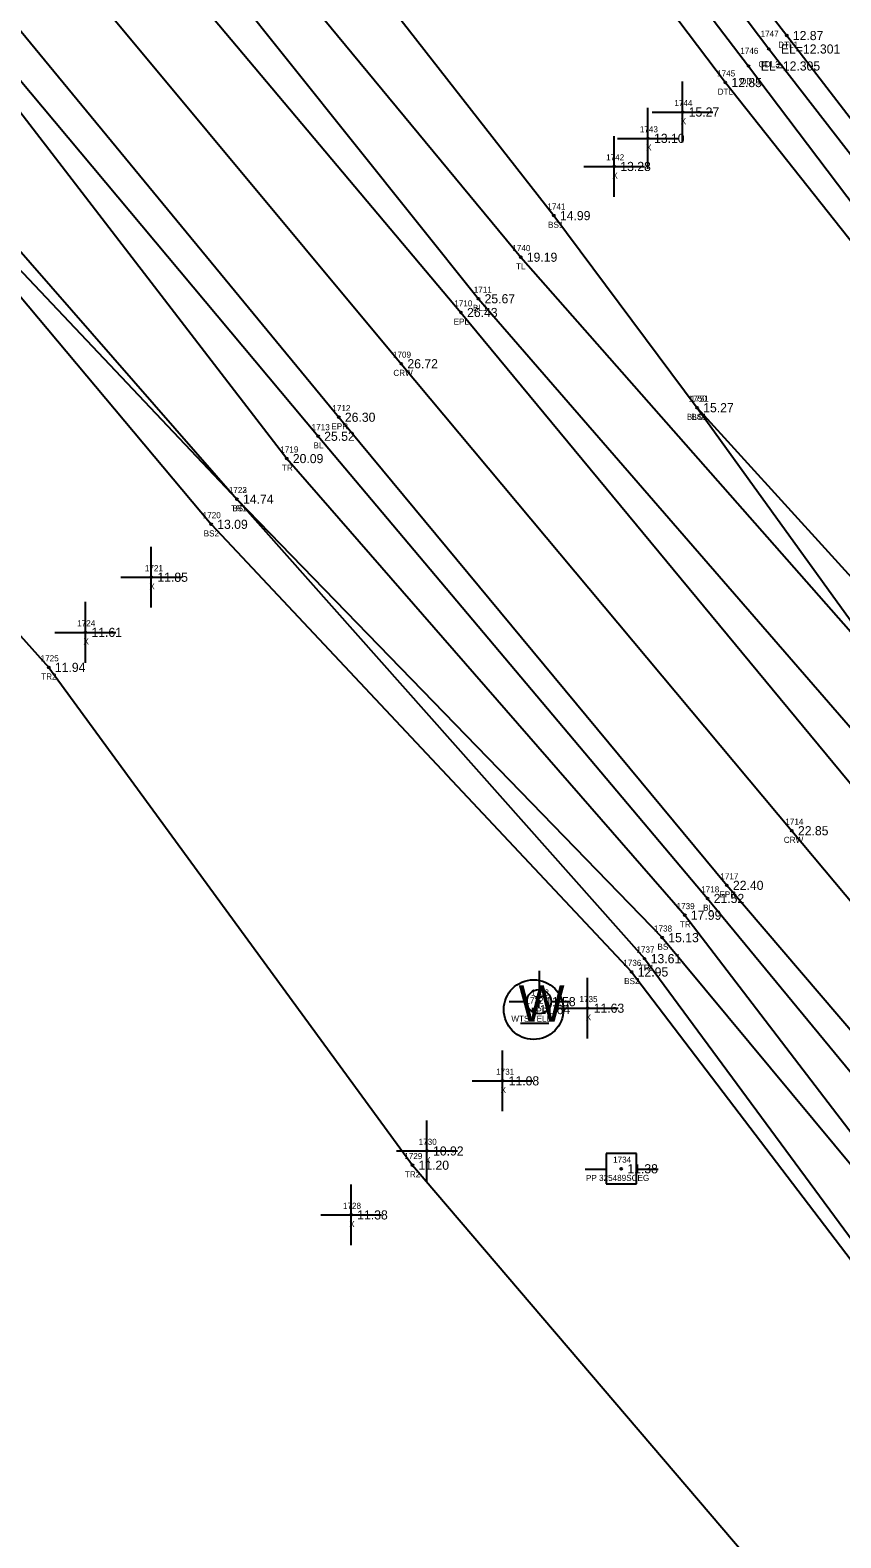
# Model space of a CAD drawing. Extents: x 2042211 to 2045853, y 303080 to 309569.
# Drawn here: x 2043815 to 2043948.3, y 305221.5 to 305469.5 of the extents above; entities that cross this region are included whole.
import ezdxf

# ---------------------------------------------------------------- set-up
doc = ezdxf.new("R2010")
doc.units = 0
for name, color, linetype in [('BR_500YR_SCOUR', 7, 'Continuous'), ('RD_DTM_BkLn1', 7, 'Continuous'), ('RD_DTM_BkLn2', 7, 'Continuous'), ('RD_DTM_BkLn_txCode', 7, 'Continuous'), ('RD_EX_H2O', 7, 'Continuous'), ('RD_EX_H2O_txCode', 7, 'Continuous'), ('RD_EX_Misc', 7, 'Continuous'), ('RD_EX_Misc_txCode', 7, 'Continuous'), ('RD_EX_Road', 7, 'Continuous'), ('RD_EX_Road_txCode', 7, 'Continuous'), ('RD_EX_TX_H2O_ELEV', 7, 'Continuous'), ('RD_EX_TX_Misc_ELEV', 7, 'Continuous'), ('RD_EX_TX_Road_ELEV', 7, 'Continuous'), ('RD_EX_TX_UT_ELEV', 7, 'Continuous'), ('RD_EX_TX_VEG_ELEV', 7, 'Continuous'), ('RD_EX_UT_txCode', 7, 'Continuous'), ('RD_EX_VEG_txCode', 7, 'Continuous'), ('RD_HC_Survey_ELEV', 7, 'Continuous'), ('RD_HC_Survey_txCode', 7, 'Continuous'), ('RD_SMD_Locator', 7, 'Continuous')]:
    doc.layers.add(name, color=color, linetype=linetype)

msp = doc.modelspace()

# ---------------------------------------------------------------- linework, layer by layer
at = {"layer": 'BR_500YR_SCOUR'}
for p, q in [((2043898.65, 305314.79), (2043898.65, 305311.72)), ((2043893.72, 305309.74), (2043896.65, 305309.74)), ((2043900.65, 305309.74), (2043903.72, 305309.74)), ((2043895.62, 305306.2), (2043900.25, 305306.2)), ((2043914.66, 305284.74), (2043909.66, 305284.74)), ((2043909.66, 305284.74), (2043909.66, 305279.74)), ((2043914.66, 305279.74), (2043914.66, 305284.74)), ((2043906.23, 305282.18), (2043909.7, 305282.18)), ((2043914.59, 305282.18), (2043918.23, 305282.18)), ((2043909.66, 305279.74), (2043914.66, 305279.74))]:
    msp.add_line(p, q, dxfattribs=at)
for points in [[(2043547.51, 305881.5), (2043539.7, 305861.32), (2043541.74, 305855.07), (2043567.73, 305828.7), (2043642.4, 305738.29), (2043706.88, 305661.84), (2043768.33, 305586.86), (2043834.29, 305506.38), (2043895.63, 305432.16), (2043964.52, 305353.99), (2044012.41, 305288.23), (2044020.96, 305286.08), (2044026.64, 305287.13), (2044039.88, 305282.36)], [(2043510.52, 305810.42), (2043502.87, 305810.61), (2043504.87, 305802.25), (2043509.11, 305791.37), (2043594.27, 305695.69), (2043658.16, 305620.89), (2043717.86, 305542.89), (2043784.35, 305466.31), (2043848.97, 305392.37), (2043916.01, 305316.79), (2043971.98, 305240.84)], [(2043510.52, 305810.42), (2043528.58, 305788.55), (2043603.52, 305706.8), (2043669.11, 305631.48), (2043746.08, 305529.27), (2043781.83, 305496.01), (2043793.11, 305482.33), (2043857.16, 305399.04), (2043922.61, 305323.93), (2043978.69, 305250.66), (2043978.39, 305246.16), (2043971.98, 305240.84)], [(2043442.97, 305737.07), (2043459.87, 305757.29), (2043500.33, 305735.55), (2043510.29, 305716.16), (2043558.94, 305666.15), (2043625.65, 305592.92), (2043688.91, 305518.94), (2043753.11, 305437.19), (2043818.03, 305364.7), (2043877.83, 305282.82), (2043938.63, 305211.62), (2044011.48, 305138.99), (2044075.86, 305057.44), (2044138.75, 304984.38), (2044203.27, 304905.13), (2044266.06, 304829.27), (2044328.58, 304748.23), (2044394.11, 304672.51), (2044456.79, 304595.02), (2044489.64, 304560.38)]]:
    msp.add_lwpolyline(points, dxfattribs=at)
for centre, radius in [((2043895.63, 305432.16), 0.15), ((2043857.16, 305399.04), 0.15), ((2043848.97, 305392.37), 0.15), ((2043848.97, 305392.37), 0.15), ((2043818.03, 305364.7), 0.15), ((2043922.61, 305323.93), 0.15), ((2043916.01, 305316.79), 0.15), ((2043897.75, 305308.41), 4.91), ((2043898.65, 305309.72), 2), ((2043897.75, 305308.41), 0.15), ((2043898.65, 305309.72), 0.15), ((2043877.83, 305282.82), 0.15), ((2043912.17, 305282.23), 0.15)]:
    msp.add_circle(centre, radius, dxfattribs=at)
at = {"layer": 'RD_DTM_BkLn1'}
for points in [[(2043537.57, 305841.2), (2043543.07, 305834.82), (2043547.67, 305836.32), (2043557.54, 305825.5), (2043571.92, 305809.49), (2043633.83, 305732.88), (2043699.09, 305656.29), (2043762.93, 305580.55), (2043827.21, 305502.36), (2043888.69, 305425.33), (2043954.53, 305349.45), (2044014.08, 305277.47), (2044018.49, 305276.45), (2044019.61, 305275.44), (2044023.1, 305269.64), (2044024.11, 305264.85), (2044081.02, 305196.95), (2044145.48, 305121.13), (2044210.56, 305044.49), (2044273.6, 304967.95), (2044321.18, 304912.75), (2044337.82, 304895.78)], [(2043528.91, 305830.2), (2043556.35, 305797.19), (2043619.96, 305720.85), (2043684.02, 305644.21), (2043747.98, 305567.9), (2043812.35, 305491.13), (2043876, 305414.64), (2043940.22, 305337.83), (2044003.86, 305261.82), (2044067.88, 305184.94), (2044131, 305108.73), (2044195.62, 305032.03), (2044259.59, 304955.88), (2044323.63, 304879.52), (2044387.48, 304802.4), (2044451.92, 304725.21), (2044515.94, 304648.42), (2044581.15, 304571.52), (2044645.01, 304495.17), (2044708.42, 304418.52), (2044772.84, 304341.13)], [(2043798.36, 305479.17), (2043862.32, 305402.71), (2043926.37, 305326.69), (2043989.74, 305249.79), (2043988.33, 305246.75), (2043991.19, 305243.51), (2043994.75, 305243.65), (2044053.09, 305173.37), (2044116.28, 305094.9), (2044180.2, 305019.52), (2044245.63, 304943.51), (2044308.37, 304866.05), (2044373.1, 304789.96), (2044438.35, 304712.62), (2044501.57, 304636.05), (2044528.47, 304600.32), (2044565.87, 304558.85), (2044630.47, 304482.97), (2044694.06, 304405.2), (2044697.06, 304397.81), (2044701.81, 304392.08), (2044707.96, 304388.87), (2044759.04, 304329.78)], [(2043924.64, 305407.41), (2043967.73, 305360.03), (2044026.58, 305285.03)]]:
    msp.add_lwpolyline(points, dxfattribs=at)
at = {"layer": 'RD_DTM_BkLn2'}
for points in [[(2043547.74, 305884.86), (2043551.89, 305882.53), (2043558.15, 305885.46), (2043596.66, 305831.05), (2043655.82, 305751.61), (2043719.21, 305673.32), (2043779.86, 305593.61), (2043842.41, 305514.12), (2043901.08, 305439), (2043924.64, 305407.41), (2043962.04, 305355.58), (2044016.29, 305283.02), (2044024.42, 305277.9)], [(2043483.64, 305794.6), (2043499.9, 305777.95), (2043515.27, 305762.9), (2043518.21, 305761.16), (2043589.07, 305691.11), (2043649.23, 305614.13), (2043716.37, 305541.69), (2043781.37, 305463.81), (2043848.97, 305392.37), (2043918.9, 305320.25), (2043979.36, 305247.54), (2043984.14, 305244.91)], [(2043781.37, 305463.81), (2043844.73, 305388.23), (2043913.87, 305314.6), (2043971.21, 305239.33)]]:
    msp.add_lwpolyline(points, dxfattribs=at)
at = {"layer": 'RD_EX_H2O'}
for points in [[(2043695.41, 305785.95), (2043753.23, 305702.74), (2043816.84, 305621.67), (2043878.98, 305542.47), (2043936.42, 305466.41), (2044001.08, 305383.06), (2044036.64, 305336.24), (2044042.32, 305312.25), (2044044.08, 305296.68), (2044037.04, 305284.58), (2044037.23, 305281.89), (2044040.11, 305279.62), (2044044.74, 305276.06), (2044050.89, 305261.28), (2044092.5, 305206.78), (2044153.45, 305129.2), (2044155.72, 305128.46), (2044158.75, 305129.8), (2044171.64, 305145.93), (2044183.17, 305157.87), (2044199.16, 305188.17), (2044208.66, 305215.31)], [(2043691.65, 305782.08), (2043750.76, 305701.1), (2043812.59, 305619.17), (2043875.5, 305539.19), (2043933.11, 305463.61), (2043996.22, 305380.1), (2044030.28, 305333.3), (2044036.73, 305312.37), (2044037.31, 305297.73), (2044030.81, 305285.38), (2044029.9, 305283.95), (2044027.87, 305283.16)], [(2043688.94, 305780.02), (2043748.1, 305697.94), (2043809.2, 305616.91), (2043872.33, 305536.25), (2043929.28, 305460.89), (2043994.32, 305378.82), (2044029.48, 305332.31), (2044031.68, 305311), (2044031.99, 305298.04), (2044028.8, 305286.25)], [(2043880.99, 305544.38), (2043939.38, 305468.62), (2044003.53, 305385.22), (2044039.35, 305337.85), (2044047.71, 305312.67), (2044046.57, 305295.78), (2044040.04, 305284.22), (2044040.55, 305281.91), (2044045.48, 305279.05), (2044047.12, 305275.75), (2044052.64, 305262.28), (2044093.07, 305207.37)]]:
    msp.add_lwpolyline(points, dxfattribs=at)
at = {"layer": 'RD_EX_Misc'}
for p, q in [((2043922.25, 305451.04), (2043922.25, 305461.04)), ((2043916.56, 305446.71), (2043916.56, 305456.71)), ((2043917.25, 305456.04), (2043927.25, 305456.04)), ((2043911.01, 305442.09), (2043911.01, 305452.09)), ((2043911.56, 305451.71), (2043921.56, 305451.71)), ((2043906.01, 305447.09), (2043916.01, 305447.09)), ((2043834.89, 305374.52), (2043834.89, 305384.52)), ((2043829.89, 305379.52), (2043839.89, 305379.52)), ((2043824.05, 305365.46), (2043824.05, 305375.46)), ((2043819.05, 305370.46), (2043829.05, 305370.46)), ((2043906.63, 305303.64), (2043906.63, 305313.64)), ((2043901.63, 305308.64), (2043911.63, 305308.64)), ((2043892.65, 305291.69), (2043892.65, 305301.69)), ((2043887.65, 305296.69), (2043897.65, 305296.69)), ((2043880.22, 305280.16), (2043880.22, 305290.16)), ((2043875.22, 305285.16), (2043885.22, 305285.16)), ((2043867.75, 305269.64), (2043867.75, 305279.64)), ((2043862.75, 305274.64), (2043872.75, 305274.64))]:
    msp.add_line(p, q, dxfattribs=at)
at = {"layer": 'RD_EX_Road'}
for points in [[(2043522.11, 305820), (2043547.67, 305789.85), (2043610.72, 305713.32), (2043674.95, 305636.32), (2043738.18, 305559.62), (2043802.42, 305482.71), (2043865.72, 305405.84), (2043929.53, 305328.85), (2043994.13, 305253.28), (2044057.4, 305176.5), (2044121.27, 305100.2), (2044185.29, 305023.54), (2044249.56, 304947.28), (2044313.31, 304870.31), (2044377.09, 304793.29), (2044442, 304716.26), (2044505.92, 304639.55), (2044570.44, 304562.35), (2044634.61, 304485.93), (2044698.46, 304409.27), (2044762.46, 304332.37)], [(2043821.87, 305499.1), (2043885.81, 305423.07), (2043949.56, 305345.93), (2044013.41, 305270.34), (2044077.97, 305194.15)]]:
    msp.add_lwpolyline(points, dxfattribs=at)
at = {"layer": 'RD_SMD_Locator'}
for centre in [(2043936.42, 305466.41), (2043939.38, 305468.62), (2043933.11, 305463.61), (2043929.28, 305460.89), (2043922.25, 305456.04), (2043916.56, 305451.71), (2043911.01, 305447.09), (2043901.08, 305439), (2043888.69, 305425.33), (2043885.81, 305423.07), (2043876, 305414.64), (2043924.64, 305407.41), (2043924.64, 305407.41), (2043865.72, 305405.84), (2043862.32, 305402.71), (2043844.73, 305388.23), (2043834.89, 305379.52), (2043824.05, 305370.46), (2043940.22, 305337.83), (2043929.53, 305328.85), (2043926.37, 305326.69), (2043918.9, 305320.25), (2043913.87, 305314.6), (2043906.63, 305308.64), (2043892.65, 305296.69), (2043880.22, 305285.16), (2043867.75, 305274.64)]:
    msp.add_circle(centre, 0.15, dxfattribs=at)

# ---------------------------------------------------------------- texts
at = {"layer": 'BR_500YR_SCOUR'}
for s, height, p in [('W', 6, (2043895.28, 305306.41)), ('T', 2, (2043897.8, 305308.67))]:
    msp.add_text(s, height=height, dxfattribs=at).set_placement(p)
at = {"layer": 'RD_DTM_BkLn_txCode'}
for s, p in [('1741', (2043900.02, 305440)), ('BS1', (2043900.13, 305437)), ('1711', (2043887.91, 305426.33)), ('BL1', (2043887.77, 305423.33)), ('1750', (2043923.25, 305408.41)), ('1751', (2043923.58, 305408.41)), ('1713', (2043861.26, 305403.71)), ('BL4A', (2043922.95, 305405.41)), ('BS1', (2043923.69, 305405.41)), ('BL', (2043861.56, 305400.71)), ('1723', (2043847.63, 305393.37)), ('1720', (2043843.34, 305389.23)), ('BS', (2043848.19, 305390.37)), ('BS2', (2043843.5, 305386.23)), ('1718', (2043925.31, 305327.69)), ('BL', (2043925.62, 305324.69)), ('1738', (2043917.55, 305321.25)), ('BS', (2043918.12, 305318.25)), ('1736', (2043912.5, 305315.6)), ('BS2', (2043912.64, 305312.6))]:
    msp.add_text(s, height=1, dxfattribs=at).set_placement(p)
at = {"layer": 'RD_EX_H2O_txCode'}
for s, p in [('1747', (2043935.07, 305468.41)), ('1746', (2043931.74, 305465.61)), ('DTL1', (2043937.97, 305466.62)), ('ODL3', (2043934.73, 305463.41)), ('1745', (2043927.93, 305461.89)), ('ODL1', (2043931.7, 305460.61)), ('DTL', (2043928.03, 305458.89))]:
    msp.add_text(s, height=1, dxfattribs=at).set_placement(p)
at = {"layer": 'RD_EX_Misc_txCode'}
for s, p in [('1744', (2043920.9, 305457.04)), ('X', (2043921.93, 305454.04)), ('1743', (2043915.22, 305452.71)), ('1742', (2043909.67, 305448.09)), ('X', (2043916.25, 305449.71)), ('X', (2043910.7, 305445.09)), ('1721', (2043833.83, 305380.52)), ('X', (2043834.57, 305377.52)), ('1724', (2043822.7, 305371.46)), ('X', (2043823.73, 305368.46)), ('1735', (2043905.29, 305309.64)), ('X', (2043906.32, 305306.64)), ('1731', (2043891.59, 305297.69)), ('X', (2043892.33, 305294.69)), ('1730', (2043878.84, 305286.16)), ('X', (2043879.91, 305283.16)), ('1728', (2043866.4, 305275.64)), ('X', (2043867.43, 305272.64))]:
    msp.add_text(s, height=1, dxfattribs=at).set_placement(p)
at = {"layer": 'RD_EX_Road_txCode'}
for s, p in [('1710', (2043884.71, 305424.07)), ('EPL', (2043884.6, 305421.07)), ('1712', (2043864.66, 305406.84)), ('EPR', (2043864.49, 305403.84)), ('1717', (2043928.46, 305329.85)), ('EPR', (2043928.3, 305326.85))]:
    msp.add_text(s, height=1, dxfattribs=at).set_placement(p)
at = {"layer": 'RD_EX_TX_H2O_ELEV'}
for s, p in [('12.87', (2043940.38, 305467.87)), ('EL=12.301', (2043938.42, 305465.66)), ('EL=12.305', (2043935.11, 305462.86)), ('12.85', (2043930.28, 305460.14))]:
    msp.add_text(s, height=1.5, dxfattribs=at).set_placement(p)
at = {"layer": 'RD_EX_TX_Misc_ELEV'}
for s, p in [('15.27', (2043923.25, 305455.29)), ('13.10', (2043917.56, 305450.96)), ('13.28', (2043912.01, 305446.34)), ('14.99', (2043902.08, 305438.25)), ('25.67', (2043889.69, 305424.58)), ('15.27', (2043925.64, 305406.66)), ('15.27', (2043925.64, 305406.66)), ('25.52', (2043863.32, 305401.96)), ('14.74', (2043849.97, 305391.62)), ('13.09', (2043845.73, 305387.48)), ('11.85', (2043835.89, 305378.77)), ('11.61', (2043825.05, 305369.71)), ('21.52', (2043927.37, 305325.94)), ('15.13', (2043919.9, 305319.5)), ('12.95', (2043914.87, 305313.85)), ('11.63', (2043907.63, 305307.89)), ('11.08', (2043893.65, 305295.94)), ('10.92', (2043881.22, 305284.41)), ('11.38', (2043868.75, 305273.89))]:
    msp.add_text(s, height=1.5, dxfattribs=at).set_placement(p)
at = {"layer": 'RD_EX_TX_Road_ELEV'}
for s, p in [('26.43', (2043886.81, 305422.32)), ('26.30', (2043866.72, 305405.09)), ('22.40', (2043930.53, 305328.1))]:
    msp.add_text(s, height=1.5, dxfattribs=at).set_placement(p)
at = {"layer": 'RD_EX_TX_UT_ELEV'}
for s, p in [('11.58', (2043899.65, 305308.97)), ('11.64', (2043898.75, 305307.66))]:
    msp.add_text(s, height=1.5, dxfattribs=at).set_placement(p)
at = {"layer": 'RD_EX_TX_VEG_ELEV'}
for s, p in [('19.19', (2043896.63, 305431.41)), ('20.09', (2043858.16, 305398.29)), ('14.74', (2043849.97, 305391.62)), ('11.94', (2043819.03, 305363.95)), ('17.99', (2043923.61, 305323.18)), ('13.61', (2043917.01, 305316.04)), ('11.20', (2043878.83, 305282.07))]:
    msp.add_text(s, height=1.5, dxfattribs=at).set_placement(p)
at = {"layer": 'RD_EX_UT_txCode'}
for s, p in [('1732', (2043896.4, 305309.41)), ('1733', (2043897.31, 305310.72)), ('TPP', (2043897.39, 305307.72)), ('WTS TELE', (2043894.09, 305306.41)), ('1734', (2043910.82, 305283.23)), ('PP 325489SCEG', (2043906.36, 305280.23))]:
    msp.add_text(s, height=1, dxfattribs=at).set_placement(p)
at = {"layer": 'RD_EX_VEG_txCode'}
for s, p in [('1740', (2043894.25, 305433.16)), ('TL', (2043894.86, 305430.16)), ('1719', (2043856.1, 305400.04)), ('TR', (2043856.37, 305397.04)), ('1722', (2043847.63, 305393.37)), ('TR1', (2043848.01, 305390.37)), ('1725', (2043816.69, 305365.7)), ('TR2', (2043816.79, 305362.7)), ('1739', (2043921.26, 305324.93)), ('TR', (2043921.81, 305321.93)), ('1737', (2043914.66, 305317.79)), ('TR1', (2043915.05, 305314.79)), ('1729', (2043876.48, 305283.82)), ('TR2', (2043876.59, 305280.82))]:
    msp.add_text(s, height=1, dxfattribs=at).set_placement(p)
at = {"layer": 'RD_HC_Survey_ELEV'}
for s, p in [('26.72', (2043877, 305413.89)), ('22.85', (2043941.22, 305337.08)), ('11.38', (2043913.17, 305281.48))]:
    msp.add_text(s, height=1.5, dxfattribs=at).set_placement(p)
at = {"layer": 'RD_HC_Survey_txCode'}
for s, p in [('1709', (2043874.62, 305415.64)), ('CRW', (2043874.69, 305412.64)), ('1714', (2043939.15, 305338.83)), ('CRW', (2043938.9, 305335.83))]:
    msp.add_text(s, height=1, dxfattribs=at).set_placement(p)

doc.saveas('drawing.dxf')
